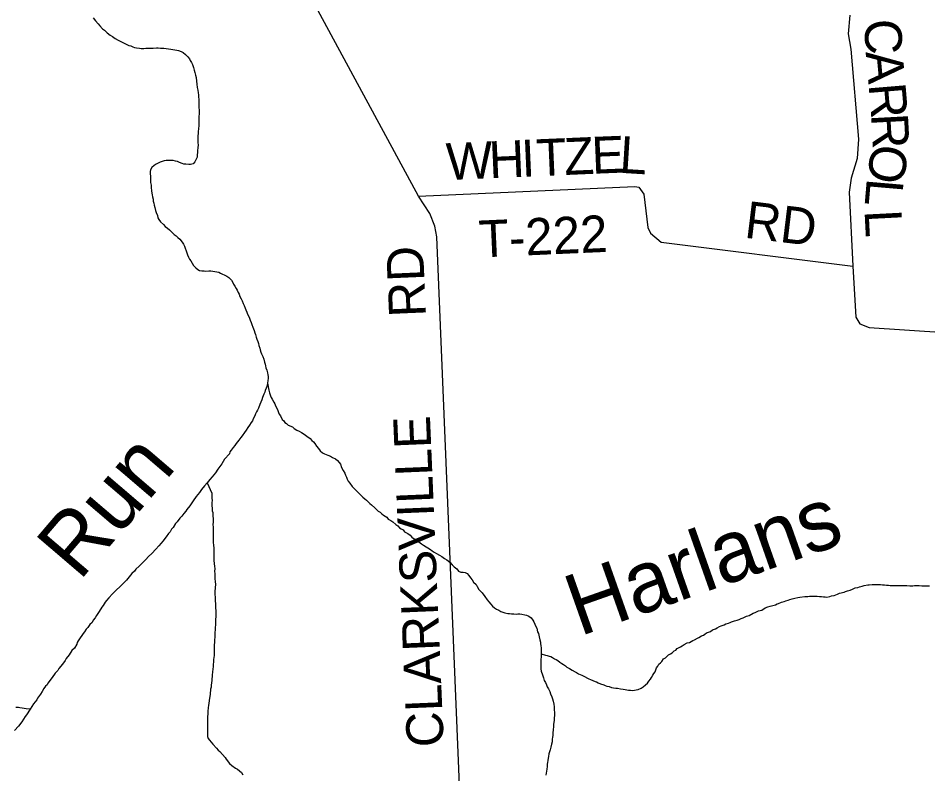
# Model space of a CAD drawing. Extents: x 0.4 to 34.4, y -2.1 to 19.9.
# Drawn here: x 7.097 to 8.499, y 16.558 to 17.722 of the extents above; entities that cross this region are included whole.
import ezdxf

# ---------------------------------------------------------------- set-up
doc = ezdxf.new("R2010")
doc.units = 0
for name, color, linetype in [('GM_X_County_Road', 7, 'Continuous'), ('GM_X_County_Road_Text', 7, 'Continuous'), ('GM_X_Minor_River', 7, 'Continuous'), ('GM_X_Minor_River_Text', 7, 'Continuous'), ('GM_X_Township_Road', 7, 'Continuous'), ('GM_X_Township_Road_Text', 7, 'Continuous')]:
    doc.layers.add(name, color=color, linetype=linetype)

msp = doc.modelspace()

# ---------------------------------------------------------------- linework, layer by layer
at = {"layer": 'GM_X_County_Road'}
msp.add_lwpolyline([(7.8306, 15.8648), (7.8323, 15.8856), (7.8597, 16.2224), (7.878, 16.4464), (7.8755, 16.4567), (7.8654, 16.4652), (7.8259, 16.4614), (7.7993, 16.4615), (7.7899, 16.4658), (7.7828, 16.4705), (7.779, 16.4915), (7.7421, 17.3856), (7.739, 17.402), (7.731, 17.4215), (7.7137, 17.448), (7.5422, 17.7657)], dxfattribs=at)
at = {"layer": 'GM_X_Minor_River'}
for points in [[(7.2123, 17.7227), (7.216, 17.7181), (7.2204, 17.7135), (7.223, 17.7104), (7.2271, 17.7057), (7.2301, 17.7038), (7.2339, 17.6999), (7.2387, 17.696), (7.2425, 17.694), (7.2466, 17.6909), (7.2508, 17.6886), (7.2549, 17.6862), (7.2594, 17.6842), (7.2636, 17.6822), (7.2677, 17.6803), (7.2704, 17.6795), (7.2734, 17.6783), (7.2764, 17.6771), (7.2795, 17.6766), (7.284, 17.6762), (7.2867, 17.6757), (7.2905, 17.6757), (7.2939, 17.676), (7.2966, 17.6759), (7.3012, 17.6762), (7.305, 17.6762), (7.31, 17.6765), (7.3126, 17.6764), (7.3161, 17.6763), (7.3187, 17.6759), (7.3214, 17.6759), (7.3248, 17.6754), (7.3286, 17.675), (7.332, 17.6745), (7.3351, 17.6741), (7.3381, 17.6737), (7.3415, 17.6732), (7.3442, 17.6724), (7.3483, 17.6708), (7.3514, 17.6696), (7.3547, 17.6665), (7.3585, 17.663), (7.3607, 17.6599), (7.3618, 17.6572), (7.364, 17.6542), (7.3654, 17.6511), (7.3672, 17.6465), (7.3683, 17.6423), (7.3693, 17.6385), (7.37, 17.6347), (7.3711, 17.6308), (7.3717, 17.6255), (7.3724, 17.6205), (7.373, 17.6156), (7.3737, 17.6114), (7.3744, 17.6072), (7.3747, 17.6041), (7.375, 17.6007), (7.3753, 17.5973)], [(7.3753, 17.5973), (7.3752, 17.5935), (7.3751, 17.5901), (7.3754, 17.5874), (7.3754, 17.584), (7.3757, 17.5809), (7.3756, 17.5756), (7.3754, 17.5703), (7.3753, 17.5657), (7.3752, 17.5619), (7.3751, 17.557), (7.3746, 17.5516), (7.3745, 17.5478), (7.3741, 17.5444), (7.374, 17.541), (7.3739, 17.5353), (7.3738, 17.5304), (7.3741, 17.5273), (7.3736, 17.5227), (7.3735, 17.5182), (7.3734, 17.5151), (7.373, 17.5125), (7.3725, 17.5083), (7.3709, 17.5042), (7.3693, 17.5011), (7.3666, 17.4981), (7.3627, 17.4971), (7.3597, 17.4968), (7.3555, 17.4972), (7.3524, 17.4976), (7.3494, 17.4985), (7.3456, 17.5001), (7.3422, 17.5013), (7.3396, 17.5021), (7.3358, 17.5029), (7.3324, 17.503), (7.3289, 17.503), (7.3251, 17.5031), (7.3217, 17.5024), (7.319, 17.5017), (7.3159, 17.5006), (7.3128, 17.4991), (7.3094, 17.4973), (7.3063, 17.4951), (7.3031, 17.4925), (7.3008, 17.4887), (7.3003, 17.486), (7.3003, 17.4826), (7.3006, 17.4788), (7.3009, 17.4754), (7.3008, 17.4727), (7.3011, 17.4689), (7.3018, 17.4651), (7.3021, 17.4621), (7.3023, 17.456), (7.3033, 17.4499), (7.304, 17.4472), (7.3047, 17.4434), (7.305, 17.4403), (7.3061, 17.4372), (7.3064, 17.4342), (7.3075, 17.4304), (7.3085, 17.4262), (7.3096, 17.4231), (7.3114, 17.4181), (7.3124, 17.4147), (7.3135, 17.412), (7.3165, 17.4085), (7.321, 17.4046), (7.3236, 17.4012), (7.327, 17.3988), (7.3299, 17.3961), (7.3341, 17.3922), (7.3374, 17.3891), (7.3404, 17.3868), (7.343, 17.3845), (7.346, 17.3817), (7.3497, 17.3771), (7.3516, 17.374), (7.353, 17.371), (7.3545, 17.3679), (7.3559, 17.3637), (7.357, 17.361), (7.3581, 17.3576), (7.3595, 17.3541), (7.361, 17.351), (7.3628, 17.3483), (7.365, 17.3449), (7.3672, 17.3414), (7.3709, 17.3375), (7.3739, 17.3352), (7.3766, 17.3336), (7.38, 17.3332), (7.3834, 17.3331), (7.3861, 17.3327), (7.3907, 17.333), (7.3937, 17.3329), (7.3971, 17.3325), (7.4002, 17.3321), (7.4028, 17.3316), (7.4059, 17.3308)], [(7.4059, 17.3308), (7.4089, 17.3296), (7.4119, 17.328), (7.4146, 17.3268), (7.4183, 17.3249), (7.4217, 17.3229), (7.4254, 17.3187), (7.4276, 17.3152), (7.4287, 17.3125), (7.4309, 17.3094), (7.4328, 17.306), (7.4342, 17.3033), (7.4361, 17.2998), (7.4375, 17.2971), (7.4386, 17.2933), (7.4404, 17.2899), (7.4419, 17.2868), (7.4437, 17.2826), (7.4451, 17.2795), (7.4466, 17.2757), (7.4476, 17.273), (7.4491, 17.2695), (7.4502, 17.2665), (7.4527, 17.2615), (7.4545, 17.2569), (7.456, 17.2534), (7.4571, 17.2504), (7.4585, 17.2465), (7.4607, 17.2412), (7.4617, 17.2377), (7.4628, 17.235), (7.4639, 17.2308), (7.4649, 17.2278), (7.466, 17.2243), (7.4671, 17.2209), (7.4678, 17.2182), (7.4692, 17.214), (7.4699, 17.2113), (7.471, 17.2079), (7.472, 17.2052), (7.4739, 17.201), (7.4753, 17.1968), (7.4767, 17.1922), (7.4774, 17.1895), (7.4781, 17.1868), (7.4788, 17.1834), (7.4799, 17.18), (7.4809, 17.1758), (7.4816, 17.1727), (7.4819, 17.17), (7.4819, 17.1674), (7.4818, 17.1639), (7.4813, 17.1598), (7.4805, 17.1564), (7.4789, 17.1522), (7.4776, 17.1488), (7.4772, 17.1461), (7.4756, 17.1428), (7.4736, 17.1378), (7.4724, 17.1344), (7.4707, 17.1307), (7.4691, 17.1273), (7.4671, 17.1216), (7.4655, 17.1186), (7.4643, 17.116), (7.4627, 17.1129), (7.4615, 17.1099), (7.4591, 17.105), (7.4579, 17.102), (7.4559, 17.0994), (7.4536, 17.0952), (7.4508, 17.0915), (7.448, 17.0877), (7.4457, 17.084), (7.4421, 17.0791), (7.4398, 17.0765), (7.437, 17.0723), (7.4347, 17.0697), (7.4331, 17.0671), (7.4307, 17.0641), (7.4284, 17.0611), (7.4249, 17.0569), (7.4233, 17.0543), (7.4224, 17.0513), (7.415, 17.0427), (7.4107, 17.0359), (7.4075, 17.0318), (7.4044, 17.0273), (7.4008, 17.022), (7.3957, 17.0156), (7.3922, 17.0115), (7.3883, 17.0063), (7.3843, 17.0018), (7.3796, 16.9961), (7.3761, 16.9916), (7.371, 16.9853), (7.3667, 16.9789), (7.3612, 16.971), (7.3568, 16.9654), (7.3553, 16.9627), (7.3521, 16.9594)], [(7.4813, 17.1598), (7.4834, 17.1491), (7.4844, 17.1449), (7.4858, 17.1407), (7.4869, 17.138), (7.4884, 17.1353), (7.491, 17.1307), (7.4924, 17.128), (7.4935, 17.1253), (7.4953, 17.1215), (7.4968, 17.118), (7.4982, 17.1149), (7.4989, 17.1123), (7.5012, 17.1096), (7.5037, 17.1042), (7.5063, 17.1019), (7.5078, 17.0992), (7.5104, 17.0976), (7.513, 17.0953), (7.5194, 17.0925), (7.5221, 17.0902), (7.5262, 17.0874), (7.53, 17.0862), (7.5337, 17.0839), (7.5375, 17.0815), (7.5416, 17.0784), (7.5469, 17.0749), (7.5495, 17.0718), (7.5521, 17.0695), (7.5539, 17.0668), (7.5565, 17.0629), (7.5595, 17.0594), (7.5625, 17.0556), (7.5658, 17.0528), (7.5692, 17.0509), (7.5741, 17.0489), (7.5783, 17.0473), (7.5813, 17.0457), (7.5858, 17.0434), (7.5888, 17.041), (7.5914, 17.0379), (7.5936, 17.0352), (7.5954, 17.0302), (7.5976, 17.0256), (7.6002, 17.0214), (7.6013, 17.0183), (7.6027, 17.0153), (7.6038, 17.0122), (7.6056, 17.0088), (7.6082, 17.0057), (7.6116, 17.0007), (7.6149, 16.9979), (7.6175, 16.9948), (7.6201, 16.9921), (7.6227, 16.9894), (7.6257, 16.9871), (7.628, 16.9844), (7.631, 16.982), (7.6336, 16.9797), (7.6362, 16.9774), (7.6388, 16.9747), (7.6414, 16.9723), (7.6463, 16.9681), (7.6493, 16.9653), (7.6519, 16.963), (7.6545, 16.9611), (7.6571, 16.9587), (7.6597, 16.9568), (7.665, 16.9533), (7.6672, 16.9506), (7.6714, 16.9482), (7.674, 16.9466), (7.6789, 16.942), (7.6819, 16.9404), (7.6845, 16.9369), (7.6871, 16.9354), (7.6901, 16.9342), (7.6923, 16.9311), (7.6976, 16.9283), (7.701, 16.9256), (7.7036, 16.9229), (7.7073, 16.9202), (7.7104, 16.9186), (7.7145, 16.9155), (7.7186, 16.9127), (7.7216, 16.9104), (7.7254, 16.908), (7.728, 16.9065), (7.7321, 16.9037), (7.7348, 16.9018), (7.7378, 16.8998), (7.7415, 16.8978), (7.746, 16.8951), (7.7498, 16.8931), (7.7539, 16.89), (7.7577, 16.8877), (7.7622, 16.8842), (7.7659, 16.8803), (7.7689, 16.8772), (7.7726, 16.8737), (7.7752, 16.8706)], [(7.3883, 17.0063), (7.3951, 16.9905), (7.3954, 16.9867), (7.3953, 16.9825), (7.3957, 16.9799), (7.3956, 16.9757), (7.3955, 16.9719), (7.3958, 16.9666), (7.3961, 16.9635), (7.3968, 16.9608), (7.397, 16.9555), (7.3973, 16.9509), (7.3972, 16.9464), (7.3971, 16.9418), (7.3974, 16.9384), (7.3973, 16.9342), (7.3975, 16.9277), (7.3975, 16.9247), (7.3974, 16.9216), (7.3976, 16.9144), (7.3979, 16.9106), (7.3982, 16.9056), (7.3985, 16.9003), (7.3983, 16.8935), (7.3982, 16.8904), (7.3985, 16.8874), (7.3992, 16.8817), (7.3995, 16.8779), (7.3998, 16.8737), (7.3997, 16.8702), (7.4, 16.8664), (7.3999, 16.8638), (7.3998, 16.8592), (7.4005, 16.8539), (7.4008, 16.8501), (7.4001, 16.839), (7.4, 16.8341), (7.4003, 16.8307), (7.4006, 16.8242), (7.4008, 16.8204), (7.4008, 16.8177), (7.4011, 16.8143), (7.4013, 16.8086), (7.4016, 16.8021), (7.401, 16.7941), (7.401, 16.7915), (7.4009, 16.7888), (7.4004, 16.7827), (7.4003, 16.7797), (7.4002, 16.7766), (7.4001, 16.7706), (7.4, 16.7679), (7.3996, 16.7649), (7.3995, 16.7599), (7.399, 16.7573), (7.3989, 16.7523), (7.3989, 16.7497), (7.3988, 16.7466), (7.3987, 16.7405), (7.3981, 16.7345), (7.3977, 16.7303), (7.3976, 16.7269), (7.3975, 16.7234), (7.3966, 16.7151), (7.3961, 16.7101), (7.3951, 16.7026), (7.3947, 16.698), (7.3942, 16.695), (7.3941, 16.6915), (7.3933, 16.6885), (7.3927, 16.6809), (7.3923, 16.6775), (7.3915, 16.6749), (7.3909, 16.6669), (7.3904, 16.6635), (7.3896, 16.6604), (7.3891, 16.654), (7.389, 16.6509), (7.3889, 16.6452), (7.3887, 16.638), (7.3886, 16.6327), (7.3888, 16.6251), (7.3888, 16.6224), (7.3887, 16.6194), (7.3886, 16.6156), (7.3897, 16.6125), (7.3919, 16.6098), (7.3967, 16.6036), (7.4027, 16.5974), (7.4049, 16.5947), (7.4079, 16.5924), (7.4116, 16.5877), (7.4157, 16.5835), (7.4172, 16.5808), (7.4228, 16.5742), (7.4261, 16.5711), (7.4317, 16.5668), (7.4348, 16.5653), (7.4381, 16.5629), (7.4411, 16.5602), (7.4429, 16.5564)], [(7.3521, 16.9594), (7.349, 16.9552), (7.3462, 16.9522), (7.3419, 16.9466), (7.3392, 16.9436), (7.3356, 16.9376), (7.3333, 16.935), (7.3309, 16.9308), (7.3286, 16.9282), (7.325, 16.9233), (7.3199, 16.9166), (7.3172, 16.9136), (7.3136, 16.9095), (7.3093, 16.9042), (7.3027, 16.8975), (7.2976, 16.8927), (7.2937, 16.8882), (7.2887, 16.8833), (7.2832, 16.8781), (7.2785, 16.8732), (7.2762, 16.8706), (7.2723, 16.8665), (7.268, 16.8616), (7.2637, 16.8567), (7.2586, 16.8511), (7.2535, 16.8463), (7.2484, 16.8414), (7.2422, 16.8355), (7.2367, 16.8295), (7.2332, 16.8254), (7.2309, 16.8224), (7.2281, 16.8175), (7.2257, 16.8148), (7.2218, 16.8081), (7.2178, 16.802), (7.2154, 16.7987), (7.2127, 16.7949), (7.2111, 16.7915), (7.2072, 16.7882), (7.2041, 16.7837), (7.2017, 16.781), (7.1989, 16.7769), (7.197, 16.7743), (7.195, 16.7713), (7.1926, 16.7675), (7.1895, 16.763), (7.1879, 16.7604), (7.1871, 16.7577), (7.1835, 16.7517), (7.1796, 16.7483), (7.1753, 16.7412), (7.1709, 16.7356), (7.1694, 16.7329), (7.165, 16.7273), (7.1595, 16.7202), (7.158, 16.7175), (7.1537, 16.7131), (7.1493, 16.7063), (7.1427, 16.698), (7.1418, 16.6954), (7.1391, 16.6932), (7.1367, 16.6898), (7.134, 16.6849), (7.1312, 16.6807), (7.1265, 16.6747), (7.1257, 16.6721), (7.1206, 16.6661), (7.1154, 16.6578), (7.1099, 16.6492), (7.1076, 16.6462), (7.1024, 16.6383), (7.0973, 16.6315), (7.0914, 16.6248)], [(7.7752, 16.8706), (7.779, 16.8686), (7.7824, 16.8686), (7.7858, 16.8681), (7.7889, 16.8665), (7.7911, 16.8635), (7.7937, 16.86), (7.7967, 16.8569), (7.7985, 16.8534), (7.8026, 16.8496), (7.8041, 16.8469), (7.8066, 16.8423), (7.8092, 16.8395), (7.8118, 16.8368), (7.8159, 16.8314), (7.8196, 16.8264), (7.8222, 16.8229), (7.8252, 16.8195), (7.8278, 16.8164), (7.8311, 16.814), (7.8338, 16.8117), (7.8375, 16.8101), (7.8409, 16.8082), (7.8439, 16.807), (7.847, 16.8061), (7.8512, 16.8053), (7.8538, 16.8053), (7.8572, 16.8048), (7.8607, 16.8044), (7.8641, 16.8043), (7.8668, 16.8046), (7.8698, 16.8046), (7.8732, 16.8041), (7.8774, 16.8033), (7.8804, 16.8025), (7.8838, 16.8009), (7.8872, 16.7986), (7.8902, 16.7951), (7.8917, 16.7924), (7.8931, 16.7889), (7.8942, 16.7863), (7.896, 16.7824), (7.8974, 16.7771), (7.8985, 16.7744), (7.8999, 16.7694), (7.9009, 16.7648), (7.9016, 16.761), (7.9019, 16.7583), (7.9023, 16.7557), (7.9029, 16.7515), (7.9029, 16.7481), (7.9027, 16.7431), (7.9026, 16.7385), (7.9022, 16.734), (7.9024, 16.7294), (7.9024, 16.7268), (7.9023, 16.7226), (7.9022, 16.7199), (7.9029, 16.7165), (7.9047, 16.7107), (7.9065, 16.7058), (7.9072, 16.7019), (7.9094, 16.6989), (7.9112, 16.695), (7.9123, 16.692), (7.9141, 16.6893), (7.9163, 16.6847), (7.9174, 16.6816), (7.9192, 16.6766), (7.9203, 16.6739), (7.9213, 16.6701), (7.9223, 16.6655), (7.9226, 16.6613), (7.9229, 16.6568), (7.9232, 16.6526), (7.9231, 16.6492), (7.9226, 16.6435), (7.9226, 16.6408), (7.9221, 16.6374), (7.922, 16.6347), (7.9216, 16.6313), (7.9214, 16.6256), (7.921, 16.6218), (7.9209, 16.6172), (7.9204, 16.6146), (7.92, 16.6115), (7.9195, 16.6074), (7.9187, 16.604), (7.9178, 16.5994), (7.9166, 16.5949), (7.9154, 16.5918), (7.9145, 16.5888), (7.9141, 16.585), (7.9136, 16.582), (7.9131, 16.5786), (7.9127, 16.5755), (7.9123, 16.5729), (7.9118, 16.5695), (7.9113, 16.5653), (7.9109, 16.5623), (7.9104, 16.5592)], [(8.2109, 16.7972), (8.214, 16.7987), (8.2194, 16.8012), (8.2232, 16.8023), (8.2297, 16.8056), (8.2324, 16.8067), (8.2375, 16.8093), (8.2428, 16.8103), (8.2482, 16.814), (8.2521, 16.8155), (8.2555, 16.8162), (8.2617, 16.818), (8.264, 16.8187), (8.2663, 16.8198), (8.2686, 16.8205), (8.2732, 16.8227), (8.277, 16.8234), (8.2797, 16.8245), (8.2832, 16.8255), (8.2859, 16.8266), (8.2893, 16.8277), (8.2916, 16.8284), (8.2939, 16.8288), (8.2985, 16.8298), (8.3016, 16.8302), (8.3092, 16.8312), (8.3115, 16.8315), (8.3138, 16.8315), (8.3165, 16.8318), (8.3196, 16.8317), (8.323, 16.8317), (8.3253, 16.8316), (8.3279, 16.8316), (8.3317, 16.8311), (8.3348, 16.8311), (8.3378, 16.8306), (8.3405, 16.8306), (8.3432, 16.8305), (8.3474, 16.8312), (8.3504, 16.8323), (8.3543, 16.833), (8.3566, 16.8337), (8.3593, 16.8348), (8.3624, 16.8363), (8.3696, 16.838), (8.3719, 16.8388), (8.375, 16.8402), (8.3789, 16.8413), (8.3827, 16.8427), (8.3866, 16.8446), (8.3908, 16.8453), (8.3935, 16.846), (8.3973, 16.8474), (8.4007, 16.8481), (8.4061, 16.8492), (8.4084, 16.8491), (8.4126, 16.8498), (8.4153, 16.8498), (8.4179, 16.8497), (8.421, 16.8497), (8.4233, 16.8496), (8.4256, 16.8496), (8.4286, 16.8495), (8.4317, 16.8491), (8.4351, 16.849), (8.4381, 16.849), (8.4408, 16.8485), (8.4438, 16.8485), (8.4488, 16.8484), (8.4534, 16.8483), (8.456, 16.8483), (8.4595, 16.8482), (8.4629, 16.8481), (8.4663, 16.8481), (8.4709, 16.848), (8.4755, 16.8479), (8.4781, 16.8482), (8.485, 16.8481), (8.4896, 16.8476), (8.4949, 16.8475), (8.498, 16.8475), (8.501, 16.8478)], [(7.9027, 16.7431), (7.9096, 16.7411), (7.9122, 16.7403), (7.9149, 16.7395), (7.9175, 16.7387), (7.9201, 16.7371), (7.9232, 16.7355), (7.9258, 16.7343), (7.9284, 16.7327), (7.9314, 16.7304), (7.9348, 16.7281), (7.9371, 16.7265), (7.9401, 16.7245), (7.9423, 16.7226), (7.9465, 16.7202), (7.9506, 16.7179), (7.9551, 16.7155), (7.9574, 16.7143), (7.9604, 16.712), (7.963, 16.7112), (7.9657, 16.71), (7.9694, 16.708), (7.974, 16.7057), (7.9762, 16.7045), (7.9789, 16.7037), (7.9826, 16.7021), (7.986, 16.7005), (7.9883, 16.6997), (7.9906, 16.6985), (7.994, 16.6966), (7.9993, 16.6953), (8.0015, 16.6941), (8.0038, 16.6933), (8.0076, 16.6925), (8.011, 16.6913), (8.0144, 16.6908), (8.0178, 16.69), (8.0205, 16.69), (8.0251, 16.6891), (8.0289, 16.6887), (8.0323, 16.6879), (8.0349, 16.6874), (8.0372, 16.687), (8.0406, 16.6869), (8.0429, 16.6865), (8.0464, 16.6868), (8.0494, 16.6875), (8.0525, 16.6882), (8.0567, 16.6901), (8.0602, 16.6919), (8.0637, 16.6953), (8.0668, 16.6979), (8.0688, 16.7009), (8.0711, 16.7039), (8.0727, 16.7065), (8.0751, 16.7099), (8.0763, 16.7125), (8.0783, 16.7152), (8.0795, 16.7182), (8.0807, 16.7216), (8.0826, 16.7238), (8.0842, 16.7272), (8.0866, 16.7291), (8.0889, 16.7313), (8.0913, 16.7351), (8.0944, 16.7366), (8.0991, 16.7414), (8.1021, 16.7429), (8.1045, 16.7447), (8.1076, 16.7477), (8.1103, 16.7488), (8.1126, 16.7514), (8.1176, 16.7536), (8.12, 16.7551), (8.1231, 16.7573), (8.1277, 16.7599), (8.1315, 16.7606), (8.1365, 16.7636), (8.1392, 16.7647), (8.1435, 16.7672), (8.1458, 16.768), (8.15, 16.7709), (8.1527, 16.772), (8.1551, 16.7731), (8.1578, 16.7753), (8.1608, 16.7764), (8.1635, 16.7775), (8.167, 16.7801), (8.1713, 16.7816), (8.174, 16.783), (8.1774, 16.7853), (8.1801, 16.786), (8.1847, 16.7878), (8.1874, 16.7893), (8.1913, 16.7903), (8.194, 16.7914), (8.1963, 16.7921), (8.2005, 16.794), (8.2047, 16.795), (8.2078, 16.7961), (8.2109, 16.7972)], [(7.1154, 16.6578), (7.1094, 16.6583), (7.1063, 16.6588), (7.1029, 16.6592), (7.0995, 16.66), (7.0972, 16.6601), (7.0934, 16.6601)], [(7.9104, 16.5592), (7.91, 16.5562)]]:
    msp.add_lwpolyline(points, dxfattribs=at)
at = {"layer": 'GM_X_Township_Road'}
for points in [[(8.3782, 17.7268), (8.3756, 17.6984), (8.3802, 17.6744), (8.3918, 17.5358), (8.3895, 17.5062), (8.3804, 17.476), (8.3775, 17.4544), (8.3829, 17.3404), (8.3876, 17.2618), (8.3936, 17.2515), (8.4083, 17.2456), (8.525, 17.2381), (8.5946, 17.2202), (8.7203, 17.1743), (9.0808, 17.0644), (9.1187, 17.0351), (9.2555, 16.8637), (9.2689, 16.846), (9.2981, 16.824), (9.424, 16.7606), (9.4844, 16.7437), (9.53, 16.7315)], [(7.7137, 17.448), (8.0472, 17.4629), (8.0533, 17.4617), (8.0608, 17.4514), (8.0673, 17.3997), (8.0714, 17.3909), (8.0875, 17.3774), (8.3829, 17.3404)]]:
    msp.add_lwpolyline(points, dxfattribs=at)

# ---------------------------------------------------------------- texts
at = {"layer": 'GM_X_County_Road_Text'}
for s, height, rotation, p in [('RD', 0.05682, 92.4687, (7.7254, 17.2628)), ('CLARKSVILLE', 0.056818, 92.4155, (7.7529, 16.6003))]:
    msp.add_text(s, height=height, rotation=rotation, dxfattribs=at).set_placement(p)
at = {"layer": 'GM_X_Minor_River_Text'}
for s, rotation, p in [('Run', 49.4613, (7.1913, 16.8538)), ('Harlans', 19.4454, (7.9618, 16.7695))]:
    msp.add_text(s, height=0.09469, rotation=rotation, dxfattribs=at).set_placement(p)
at = {"layer": 'GM_X_Township_Road_Text'}
for s, height, rotation, p in [('C', 0.0568, 272.1747, (8.4007, 17.72)), ('A', 0.0568, 275.178, (8.4027, 17.6701)), ('R', 0.0568, 274.7594, (8.4072, 17.6204)), ('R', 0.0568, 273.0809, (8.411, 17.5744)), ('H', 0.0568, 2.4815, (7.8234, 17.4756)), ('I', 0.0568, 2.4844, (7.8733, 17.4778)), ('T', 0.0568, 2.4821, (7.8966, 17.4788)), ('Z', 0.0568, 2.4821, (7.9391, 17.4806)), ('E', 0.0568, 2.2976, (7.9815, 17.4825)), ('L', 0.0568, 356.475, (8.0224, 17.4842)), ('W', 0.0568, 2.4825, (7.7576, 17.4728)), ('O', 0.0568, 260.4221, (8.4137, 17.5311)), ('L', 0.0568, 265.1261, (8.4048, 17.4767)), ('RD', 0.05682, 353.0591, (8.2146, 17.3843)), ('L', 0.0568, 272.9621, (8.401, 17.4259)), ('T-222', 0.05682, 2.5269, (7.8079, 17.3536))]:
    msp.add_text(s, height=height, rotation=rotation, dxfattribs=at).set_placement(p)

doc.saveas('drawing.dxf')
